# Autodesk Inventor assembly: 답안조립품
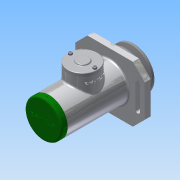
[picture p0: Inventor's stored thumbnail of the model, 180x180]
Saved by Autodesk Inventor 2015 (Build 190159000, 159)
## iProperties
Created: 2017-10
Part Number: 답안조립품
Document SubType Name: Assembly
Designer: Administrator
Author: Administrator
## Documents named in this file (20)
- C:\Users\Administrator\Desktop\471007V1002\답안조립품.iam
- C:\Users\Administrator\Desktop\471007V1002\본체.ipt
- C:\Users\Administrator\Desktop\471007V1002\사이드 커버.ipt
- 사이드 커버.ipt
- C:\Users\Administrator\Desktop\471007V1002\축.ipt
- C:\Users\Administrator\Desktop\471007V1002\멈춤링 15 x 1.ipt
- C:\Users\Administrator\Desktop\471007V1002\멈춤링 35x1.6.ipt
- C:\Users\Administrator\Desktop\471007V1002\베어링 15 x 35 x 11.ipt
- C:\Users\Administrator\Desktop\471007V1002\부시1.ipt
- C:\Users\Administrator\Desktop\471007V1002\부시2.ipt
- C:\Users\Administrator\Desktop\471007V1002\와셔 10x21.ipt
- C:\Users\Administrator\Desktop\471007V1002\너트 M10.ipt
- C:\Users\Administrator\Desktop\471007V1002\오일 실 15 25 7.ipt
- C:\Users\Administrator\Desktop\471007V1002\키 4 x 4 x 18.ipt
- C:\Users\Administrator\Desktop\471007V1002\V-벨트풀리.ipt
- C:\Users\Administrator\Desktop\471007V1002\와셔 4x16.ipt
- C:\Users\Administrator\Desktop\471007V1002\볼트 M4 x 10.ipt
- C:\Users\Administrator\Desktop\471007V1002\탑 커버.ipt
- C:\Users\Administrator\Desktop\471007V1002\와셔 3x6.ipt
- C:\Users\Administrator\Desktop\471007V1002\십자볼트 M3 x 10.ipt
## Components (2 placed, 2 different names)
1. V-벨트풀리:1
2. ISO 4017 M4 x 10:1
